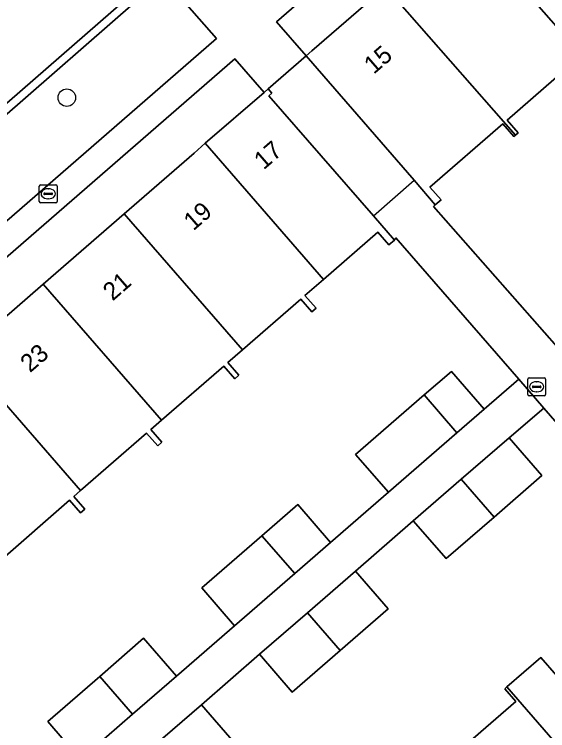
# Model space of a CAD drawing. Extents: x 155887 to 156869, y 383880 to 384678.
# Drawn here: x 156533.45 to 156563.24, y 384115.53 to 384155.57 of the extents above; entities that cross this region are included whole.
import ezdxf

# ---------------------------------------------------------------- set-up
doc = ezdxf.new("R2010")
doc.units = 0
for name, color, linetype in [('IMGEO_Boom', 7, 'Continuous'), ('IMGEO_Brandkraan', 7, 'Continuous'), ('IMGEO_Erf', 7, 'Continuous'), ('IMGEO_Pand', 7, 'Continuous'), ('IMGEO_Pand_nummerreeks', 7, 'Continuous'), ('IMGEO_Pand_overbouw', 7, 'Continuous'), ('IMGEO_Parkeervlak_open', 7, 'Continuous'), ('IMGEO_Rijbaan_lokaal_gesloten', 7, 'Continuous'), ('IMGEO_Rijbaan_lokaal_open', 7, 'Continuous'), ('IMGEO_Rioolput', 7, 'Continuous'), ('IMGEO_Voetpad_open', 7, 'Continuous')]:
    doc.layers.add(name, color=color, linetype=linetype)

msp = doc.modelspace()

# ---------------------------------------------------------------- linework, layer by layer
at = {"layer": 'IMGEO_Boom'}
msp.add_circle((156536.374, 384150.919), 0.489, dxfattribs=at)
at = {"layer": 'IMGEO_Brandkraan'}
for p, q in [((156534.838, 384145.117), (156534.838, 384145.969)), ((156534.913, 384146.043), (156535.765, 384146.043)), ((156535.326, 384145.823), (156535.351, 384145.823)), ((156535.839, 384145.969), (156535.839, 384145.117)), ((156535.097, 384145.537), (156535.097, 384145.549)), ((156535.535, 384145.5), (156535.137, 384145.5)), ((156535.14, 384145.586), (156535.538, 384145.586)), ((156535.349, 384145.263), (156535.324, 384145.263)), ((156535.581, 384145.549), (156535.581, 384145.537)), ((156535.765, 384145.043), (156534.913, 384145.043))]:
    msp.add_line(p, q, dxfattribs=at)
for points in [[(156534.838, 384145.117), (156534.838, 384145.969)], [(156534.913, 384146.043), (156535.765, 384146.043)], [(156535.839, 384145.969), (156535.839, 384145.117)], [(156535.765, 384145.043), (156534.913, 384145.043)]]:
    msp.add_lwpolyline(points, dxfattribs=at)
for centre, radius, start, end in [((156534.915, 384145.967), 0.0765, 91.552, 178.448), ((156534.915, 384145.967), 0.0765, 91.552, 178.448), ((156535.763, 384145.967), 0.0765, 1.552, 88.448), ((156535.763, 384145.967), 0.0765, 1.552, 88.448), ((156535.137, 384145.546), 0.0403, 85.8775, 175.7526), ((156535.134, 384145.536), 0.0366, 178.938, 274.7102), ((156535.538, 384145.543), 0.043, 264.8664, 352.4533), ((156535.542, 384145.548), 0.0386, 1.7309, 96.639), ((156534.915, 384145.119), 0.0765, 181.552, 268.448), ((156534.915, 384145.119), 0.0765, 181.552, 268.448), ((156535.763, 384145.119), 0.0765, 271.552, 358.448), ((156535.763, 384145.119), 0.0765, 271.552, 358.448)]:
    msp.add_arc(centre, radius, start, end, dxfattribs=at)
for centre, major_axis, ratio, start_param, end_param in [((156535.325, 384145.543), (-0.387, 0.002), 0.722429, 4.712389, 7.853982), ((156535.35, 384145.543), (-0.39, 0.002), 0.717154, 1.570796, 4.712389)]:
    msp.add_ellipse(centre, major_axis=major_axis, ratio=ratio, start_param=start_param, end_param=end_param, dxfattribs=at)
at = {"layer": 'IMGEO_Erf'}
for points in [[(156558.5, 384160.86), (156562.846, 384164.634), (156567.191, 384168.406), (156571.536, 384172.18), (156575.882, 384175.953), (156580.211, 384179.713), (156584.274, 384183.241), (156584.591, 384183.516), (156582.952, 384185.404), (156548.094, 384155.162), (156549.746, 384153.257), (156550.063, 384153.533), (156554.174, 384157.103)], [(156539.585, 384144.431), (156543.483, 384147.822), (156544.113, 384148.367), (156547.396, 384151.209), (156545.76, 384153.09), (156515.299, 384126.614), (156516.933, 384124.731), (156517.263, 384125.018), (156521.489, 384128.694), (156526.003, 384132.619), (156530.53, 384136.557), (156535.057, 384140.494)]]:
    msp.add_lwpolyline(points, close=True, dxfattribs=at)
for points in [[(156565.036, 384153.196), (156560.967, 384149.66), (156561.583, 384148.95), (156561.441, 384148.826), (156561.349, 384148.746), (156560.732, 384149.455), (156556.663, 384145.919), (156557.279, 384145.209), (156556.961, 384144.933), (156556.855, 384144.826), (156563.743, 384137.002)], [(156537.144, 384113.927), (156535.309, 384116.04), (156538.214, 384118.563), (156540.668, 384120.694), (156542.503, 384118.581), (156545.749, 384121.4), (156543.914, 384123.513), (156547.274, 384126.431), (156549.273, 384128.167), (156551.108, 384126.054), (156554.338, 384128.859), (156552.505, 384130.97), (156556.337, 384134.297), (156557.857, 384135.617), (156559.69, 384133.506), (156561.617, 384135.18), (156554.762, 384143.072), (156554.683, 384142.957), (156554.366, 384142.681), (156553.749, 384143.391), (156550.722, 384140.76), (156549.679, 384139.853), (156550.296, 384139.143), (156550.061, 384138.938), (156549.444, 384139.648), (156546.193, 384136.824), (156545.374, 384136.112), (156545.99, 384135.401), (156545.756, 384135.197), (156545.139, 384135.907), (156541.665, 384132.887), (156541.07, 384132.37), (156541.686, 384131.659), (156541.452, 384131.455), (156540.835, 384132.165), (156537.136, 384128.952), (156536.764, 384128.628), (156537.38, 384127.917), (156537.146, 384127.713), (156536.529, 384128.423), (156532.609, 384125.015)], [(156571.475, 384123.833), (156563.019, 384133.568), (156561.079, 384131.906), (156562.912, 384129.795), (156560.24, 384127.475), (156557.56, 384125.147), (156555.727, 384127.258), (156552.497, 384124.453), (156554.332, 384122.34), (156551.651, 384120.012), (156548.973, 384117.686), (156547.138, 384119.799), (156543.892, 384116.981), (156545.727, 384114.868)], [(156557.402, 384113.632), (156561.451, 384117.156), (156560.835, 384117.863), (156560.961, 384117.973), (156562.856, 384119.628), (156564.613, 384117.608)]]:
    msp.add_lwpolyline(points, dxfattribs=at)
at = {"layer": 'IMGEO_Pand'}
for points in [[(156558.5, 384160.86), (156565.766, 384152.585), (156565.887, 384152.691), (156565.271, 384153.401), (156569.34, 384156.937), (156569.957, 384156.228), (156570.088, 384156.342), (156562.846, 384164.634)], [(156558.5, 384160.86), (156554.174, 384157.103), (156561.441, 384148.826), (156561.583, 384148.95), (156560.967, 384149.66), (156565.036, 384153.196), (156565.653, 384152.487), (156565.766, 384152.585)], [(156554.174, 384157.103), (156550.063, 384153.533), (156549.746, 384153.257), (156555.775, 384146.301), (156556.961, 384144.933), (156557.279, 384145.209), (156556.663, 384145.919), (156560.732, 384149.455), (156561.349, 384148.746), (156561.441, 384148.826)], [(156550.722, 384140.76), (156553.749, 384143.391), (156554.366, 384142.681), (156554.683, 384142.957), (156553.498, 384144.317), (156547.661, 384151.015), (156547.827, 384151.16), (156547.618, 384151.401), (156547.396, 384151.209), (156544.113, 384148.367)], [(156546.193, 384136.824), (156549.444, 384139.648), (156550.061, 384138.938), (156550.296, 384139.143), (156549.679, 384139.853), (156550.722, 384140.76), (156544.113, 384148.367), (156543.483, 384147.822), (156539.585, 384144.431)], [(156535.057, 384140.494), (156541.665, 384132.887), (156545.139, 384135.907), (156545.756, 384135.197), (156545.99, 384135.401), (156545.374, 384136.112), (156546.193, 384136.824), (156539.585, 384144.431)], [(156530.53, 384136.557), (156537.136, 384128.952), (156540.835, 384132.165), (156541.452, 384131.455), (156541.686, 384131.659), (156541.07, 384132.37), (156541.665, 384132.887), (156535.057, 384140.494)], [(156530.53, 384136.557), (156526.003, 384132.619), (156532.609, 384125.015), (156536.529, 384128.423), (156537.146, 384127.713), (156537.38, 384127.917), (156536.764, 384128.628), (156537.136, 384128.952)], [(156558.171, 384132.187), (156559.69, 384133.506), (156557.857, 384135.617), (156556.337, 384134.297)], [(156558.171, 384132.187), (156556.337, 384134.297), (156552.505, 384130.97), (156554.338, 384128.859)], [(156558.407, 384129.585), (156560.24, 384127.475), (156562.912, 384129.795), (156561.079, 384131.906)], [(156558.407, 384129.585), (156555.727, 384127.258), (156557.56, 384125.147), (156560.24, 384127.475)], [(156549.109, 384124.318), (156551.108, 384126.054), (156549.273, 384128.167), (156547.274, 384126.431)], [(156549.109, 384124.318), (156547.274, 384126.431), (156543.914, 384123.513), (156545.749, 384121.4)], [(156549.818, 384122.126), (156551.651, 384120.012), (156554.332, 384122.34), (156552.497, 384124.453)], [(156549.818, 384122.126), (156547.138, 384119.799), (156548.973, 384117.686), (156551.651, 384120.012)], [(156540.05, 384116.45), (156542.503, 384118.581), (156540.668, 384120.694), (156538.214, 384118.563)], [(156567.005, 384119.687), (156564.613, 384117.608), (156562.856, 384119.628), (156560.961, 384117.973), (156568.188, 384109.654), (156572.48, 384113.384)], [(156540.05, 384116.45), (156538.214, 384118.563), (156535.309, 384116.04), (156537.144, 384113.927)], [(156568.188, 384109.654), (156560.961, 384117.973), (156560.835, 384117.863), (156561.451, 384117.156), (156557.402, 384113.632), (156556.785, 384114.341), (156556.662, 384114.234), (156563.88, 384105.911)], [(156541.204, 384114.647), (156543.039, 384112.533), (156545.727, 384114.868), (156543.892, 384116.981)]]:
    msp.add_lwpolyline(points, close=True, dxfattribs=at)
at = {"layer": 'IMGEO_Pand_overbouw'}
msp.add_lwpolyline([(156553.498, 384144.317), (156555.775, 384146.301), (156549.746, 384153.257), (156547.618, 384151.401), (156547.827, 384151.16), (156547.661, 384151.015)], close=True, dxfattribs=at)
at = {"layer": 'IMGEO_Parkeervlak_open'}
msp.add_lwpolyline([(156513.048, 384132.66), (156516.007, 384129.242), (156544.745, 384154.214), (156543.082, 384156.104), (156541.747, 384157.621), (156540.249, 384156.313), (156532.739, 384149.758)], close=True, dxfattribs=at)
at = {"layer": 'IMGEO_Rijbaan_lokaal_gesloten'}
msp.add_lwpolyline([(156529.304, 384160.02), (156529.278, 384160.045), (156525.991, 384157.507), (156528.801, 384154.278), (156530.14, 384152.739), (156532.437, 384150.105), (156545.367, 384161.393), (156577.123, 384188.995), (156578.645, 384190.254), (156578.666, 384190.271), (156582.015, 384192.761), (156582.677, 384193.231), (156583.575, 384193.809), (156583.649, 384193.857)], dxfattribs=at)
at = {"layer": 'IMGEO_Rijbaan_lokaal_open'}
msp.add_lwpolyline([(156577.43, 384188.652), (156578.942, 384189.903), (156579.075, 384190.002), (156582.273, 384192.38), (156582.956, 384192.863), (156583.862, 384193.448), (156583.575, 384193.809), (156582.677, 384193.231), (156582.015, 384192.761), (156578.666, 384190.271), (156578.645, 384190.254), (156577.123, 384188.995), (156545.367, 384161.393), (156532.437, 384150.105), (156532.739, 384149.758), (156540.249, 384156.313), (156541.747, 384157.621), (156544.174, 384159.741), (156545.669, 384161.046)], close=True, dxfattribs=at)
at = {"layer": 'IMGEO_Rioolput'}
for p, q in [((156562.196, 384135.254), (156563.048, 384135.254)), ((156562.121, 384134.328), (156562.121, 384135.18)), ((156562.609, 384135.034), (156562.634, 384135.034)), ((156563.122, 384135.18), (156563.122, 384134.328)), ((156562.38, 384134.748), (156562.38, 384134.76)), ((156562.818, 384134.711), (156562.42, 384134.711)), ((156562.423, 384134.797), (156562.821, 384134.797)), ((156562.632, 384134.474), (156562.607, 384134.474)), ((156562.864, 384134.76), (156562.864, 384134.748)), ((156563.048, 384134.254), (156562.196, 384134.254))]:
    msp.add_line(p, q, dxfattribs=at)
for points in [[(156562.196, 384135.254), (156563.048, 384135.254)], [(156562.121, 384134.328), (156562.121, 384135.18)], [(156563.122, 384135.18), (156563.122, 384134.328)], [(156563.048, 384134.254), (156562.196, 384134.254)]]:
    msp.add_lwpolyline(points, dxfattribs=at)
for centre, radius, start, end in [((156562.198, 384135.178), 0.0765, 91.552, 178.448), ((156562.198, 384135.178), 0.0765, 91.552, 178.448), ((156563.046, 384135.178), 0.0765, 1.552, 88.448), ((156563.046, 384135.178), 0.0765, 1.552, 88.448), ((156562.42, 384134.757), 0.0403, 85.8775, 175.7526), ((156562.417, 384134.747), 0.0366, 178.938, 274.7102), ((156562.821, 384134.754), 0.043, 264.8664, 352.4533), ((156562.825, 384134.759), 0.0386, 1.7309, 96.639), ((156562.198, 384134.33), 0.0765, 181.552, 268.448), ((156562.198, 384134.33), 0.0765, 181.552, 268.448), ((156563.046, 384134.33), 0.0765, 271.552, 358.448), ((156563.046, 384134.33), 0.0765, 271.552, 358.448)]:
    msp.add_arc(centre, radius, start, end, dxfattribs=at)
for centre, major_axis, ratio, start_param, end_param in [((156562.608, 384134.754), (-0.387, 0.002), 0.722429, 4.712389, 7.853982), ((156562.633, 384134.754), (-0.39, 0.002), 0.717154, 1.570796, 4.712389)]:
    msp.add_ellipse(centre, major_axis=major_axis, ratio=ratio, start_param=start_param, end_param=end_param, dxfattribs=at)
at = {"layer": 'IMGEO_Voetpad_open'}
for points in [[(156543.082, 384156.104), (156544.745, 384154.214), (156516.007, 384129.242), (156514.28, 384127.716), (156510.697, 384131.927), (156509.058, 384130.495), (156512.79, 384126.202), (156513.627, 384125.239), (156515.299, 384126.614), (156545.76, 384153.09), (156547.396, 384151.209), (156547.618, 384151.401), (156549.746, 384153.257), (156548.094, 384155.162), (156582.952, 384185.404)], [(156541.204, 384114.647), (156543.892, 384116.981), (156547.138, 384119.799), (156549.818, 384122.126), (156552.497, 384124.453), (156555.727, 384127.258), (156558.407, 384129.585), (156561.079, 384131.906), (156563.019, 384133.568), (156561.617, 384135.18), (156559.69, 384133.506), (156558.171, 384132.187), (156554.338, 384128.859), (156551.108, 384126.054), (156549.109, 384124.318), (156545.749, 384121.4), (156542.503, 384118.581), (156540.05, 384116.45), (156537.144, 384113.927)]]:
    msp.add_lwpolyline(points, dxfattribs=at)
msp.add_lwpolyline([(156565.143, 384135.411), (156563.743, 384137.002), (156556.855, 384144.826), (156556.961, 384144.933), (156555.775, 384146.301), (156549.746, 384153.257), (156547.618, 384151.401), (156547.827, 384151.16), (156547.661, 384151.015), (156553.498, 384144.317), (156554.683, 384142.957), (156554.762, 384143.072), (156561.617, 384135.18), (156563.019, 384133.568), (156571.475, 384123.833), (156571.374, 384123.74), (156571.489, 384123.608), (156576.761, 384117.53), (156576.924, 384117.676), (156577.132, 384117.425), (156579.234, 384119.292), (156573.771, 384125.581), (156572.041, 384127.575)], close=True, dxfattribs=at)

# ---------------------------------------------------------------- texts
at = {"layer": 'IMGEO_Pand_nummerreeks'}
for s, rotation, p in [('15', 40.9703, (156553.517, 384152.188)), ('17', 40.8774, (156547.373, 384146.85)), ('19', 40.9951, (156543.445, 384143.442)), ('21', 41.0141, (156538.935, 384139.519)), ('23', 41.0141, (156534.322, 384135.508))]:
    msp.add_text(s, height=1, rotation=rotation, dxfattribs=at).set_placement(p)

doc.saveas('drawing.dxf')
